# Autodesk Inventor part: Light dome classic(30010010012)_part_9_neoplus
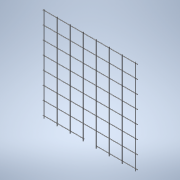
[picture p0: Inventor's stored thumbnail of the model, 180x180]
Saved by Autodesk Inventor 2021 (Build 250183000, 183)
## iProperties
Created: 2026-04
Part Number: Light dome classic(30010010012)_part_9_neoplus
Material: Generic
Catalog Web Link: www.3dfindit.com
Description: Light dome classic_part_9_neoplus-
Vendor: KINGSPAN
Document SubType Name: Modeling
Designer: psAdmin
Manufacturer: KINGSPAN
Mass: 225.585 g
Surface Area: 1814.1 cm^2
Volume: 225.585 cm^3
Density: 1 g/cm^3
Appearance: PSOLRGB-255-255-255
Category: PARTsolutions
Company: KINGSPAN
Title: Light dome classic(30010010012)_part_9_neoplus
Author: Cadenas PARTsolutions
PSOL_IDENT_0: {$CADENAS_DATA/23d-libs/kingspan_kla/light_dome_classic_neoplus/parts/part_9.prj},278 {VTYP=3D},{NB=
PSOL_IDENT_1: Light dome classic(30010010012)_part_9_neoplus},{LINA=Light dome classic(30010010012)_part_9_neoplus
PSOL_IDENT_2: },{NN=Light dome classic_part_9_neoplus},{DATE=15.07.2024 10:56:16},{GEOMDATE=28.06.2024 12:22:18},{
PSOL_IDENT_3: VERSION=},{LINEID=10},{WBVAR=LODLEVEL,L,W,DP,OP},{WBNUMERIC=W}  {NB=Light dome classic(30010010012)_
PSOL_IDENT_4: part_9_neoplus},{LINA=Light dome classic(30010010012)_part_9_neoplus},{KT=DUMMY},{IDNR=},{PN=Light d
PSOL_IDENT_5: ome classic},{LODLEVEL=300},{L=100},{W=100},{WX=100,150,200,250,300},{LX=1000},{XWX=1000},{DP=1},{OP
PSOL_IDENT_6: X='1','manualy','2','Linear drive 300 mm stroke 24 V and 230 V','3','Linear drive 500 mm stroke 24 V
PSOL_IDENT_7: and 230 V','4','Linear drive 750 mm stroke 24 V and 230 V'},{OP=2},{DRIVE=1},{DPX='1', 'Natural ven
PSOL_IDENT_8: tilation', '2' , 'NSHEV (natural smoke, heat exhaust ventilation)', '3', 'Fixed','4','NSHE'}
NB: Light dome classic(30010010012)_part_9_neoplus
NN: Light dome classic_part_9_neoplus
NBSYN: $PN.($LODLEVEL.$L.$W.$DP.$OP.)_part_9_neoplus
LINA: Light dome classic(30010010012)_part_9_neoplus
CATALOG: Light + Air
PN: Light dome classic
LODLEVEL: 300
L: 100
W: 100
DP: Natural ventilation
OP: Linear drive 300 mm stroke 24 V and 230 V
SUPPLIER: KINGSPAN
ARTICLENO: Light dome classic(30010010012)_part_9_neoplus
BOMINFO: Light dome classic(30010010012)_part_9_neoplus
CREATOR: CADENAS GmbH
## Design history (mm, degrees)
sketch "Sketch_8"
  geometry: C1 r 2.5 at (350, 263.34); 1 further point
  constraints: 1 centre point
extrude "Extrusion1" join sketch "Sketch_8" stored distance "d0" = 725; taper "d1" = 0 deg
sketch "Sketch_1"
  geometry: C1 r 2.5 at (-350, 268.32); 1 further point
  constraints: 1 centre point
extrude "Extrusion2" join sketch "Sketch_1" stored distance "d2" = 725; taper "d3" = 0 deg
pattern_linear "Rectangular Pattern1" dims "d6" = 100, "d9" = 0
sketch "Sketch_2"
  geometry: C1 r 2.5 at (250, 263.34); 1 further point
  constraints: 1 centre point
extrude "Extrusion3" join sketch "Sketch_2" stored distance "d10" = 725; taper "d11" = 0 deg
pattern_linear "Rectangular Pattern2" dims "d14" = 100, "d17" = 0
sketch "Sketch_9"
  geometry: L1 (-10, -278.32)-(10, -278.32); L2 (10, -278.32)-(10, -258.32); L3 (10, -258.32)-(-10, -258.32); L4 (-10, -258.32)-(-10, -278.32)
  constraints: 8 end point
extrude "Extrusion4" cut sketch "Sketch_9" stored distance "d18" = 220; taper "d19" = 0 deg
sketch "Sketch_7"
  geometry: L1 (-268.33, -345)-(-268.33, -355); L2 (-268.33, -355)-(-258.33, -355); L3 (-258.33, -355)-(-258.33, -345); L4 (-258.33, -345)-(-268.33, -345)
  constraints: 8 end point
extrude "Extrusion5" cut sketch "Sketch_7" stored distance "d20" = 95; taper "d21" = 0 deg
node "IP_9_XY"
node "IP_9_YZ"
node "IP_9_ZX"
node "IP_9_X"
node "IP_9_Y"
node "IP_9_Z"
node "IP_9_Center"
body "Solid1"
